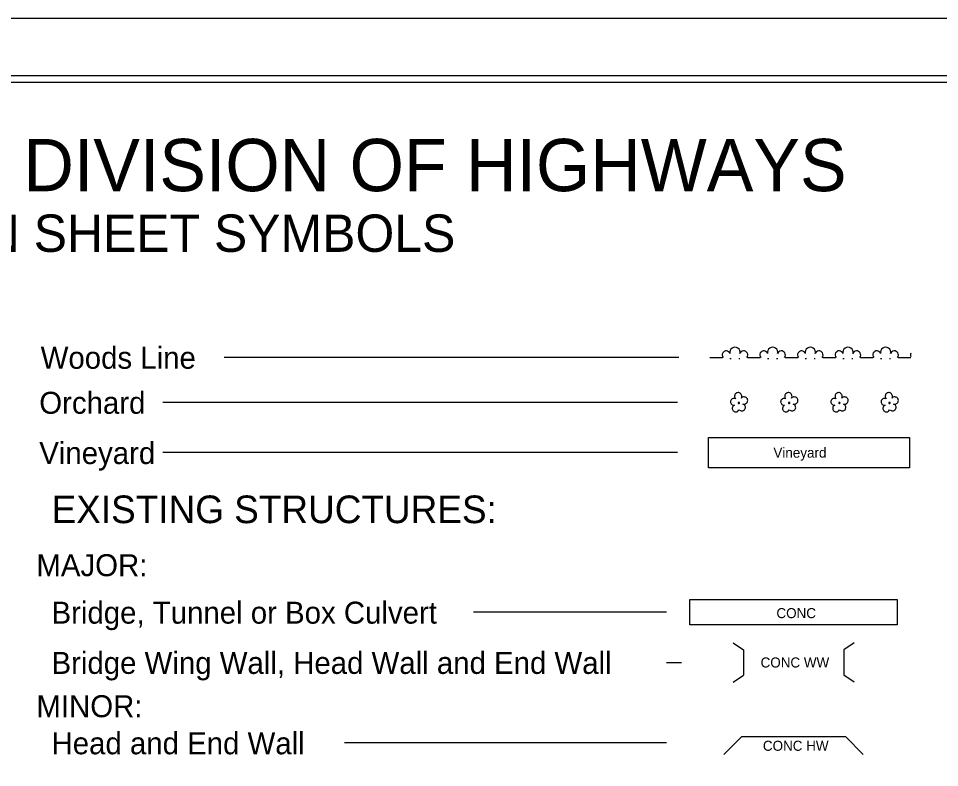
# Model space of a CAD drawing. Extents: x 2594871.4 to 2594905.1, y 784137.6 to 784159.6.
# Drawn here: x 2594889.82 to 2594897.02, y 784153.71 to 784159.56 of the extents above; entities that cross this region are included whole.
import ezdxf

# ---------------------------------------------------------------- set-up
doc = ezdxf.new("R2010")
doc.units = 0
for name, color, linetype in [('Default', 7, 'Continuous'), ('Sheet Plot Border Inside CELL', 7, 'Continuous'), ('Sheet Plot Border Outside CELL', 7, 'Continuous'), ('Sheet Symbology CELL', 7, 'Continuous')]:
    doc.layers.add(name, color=color, linetype=linetype)

msp = doc.modelspace()

# ---------------------------------------------------------------- linework, layer by layer
at = {"layer": 'Default'}
for p, q in [((2594894.9813, 784156.9155), (2594891.4285, 784156.9155)), ((2594895.2244, 784156.9155), (2594895.3225, 784156.9155)), ((2594895.3804, 784156.9057), (2594895.3902, 784156.9057)), ((2594895.449, 784156.9057), (2594895.4588, 784156.9057)), ((2594895.5187, 784156.9155), (2594895.6167, 784156.9155)), ((2594895.6746, 784156.9057), (2594895.6844, 784156.9057)), ((2594895.7433, 784156.9057), (2594895.7531, 784156.9057)), ((2594895.8129, 784156.9155), (2594895.911, 784156.9155)), ((2594895.9688, 784156.9057), (2594895.9786, 784156.9057)), ((2594896.0375, 784156.9057), (2594896.0473, 784156.9057)), ((2594896.1071, 784156.9155), (2594896.2052, 784156.9155)), ((2594896.2631, 784156.9057), (2594896.2729, 784156.9057)), ((2594896.3317, 784156.9057), (2594896.3415, 784156.9057)), ((2594896.4014, 784156.9155), (2594896.4994, 784156.9155)), ((2594896.5573, 784156.9057), (2594896.5671, 784156.9057)), ((2594896.626, 784156.9057), (2594896.6358, 784156.9057)), ((2594896.6956, 784156.9155), (2594896.7937, 784156.9155)), ((2594894.9703, 784156.5639), (2594890.9503, 784156.5639)), ((2594894.9703, 784156.1716), (2594890.9503, 784156.1716)), ((2594894.8856, 784154.9259), (2594893.3758, 784154.9259)), ((2594895.4044, 784154.6878), (2594895.4849, 784154.6316)), ((2594896.3499, 784154.6878), (2594896.2695, 784154.6316)), ((2594895.4849, 784154.6316), (2594895.4849, 784154.4355)), ((2594896.2695, 784154.6316), (2594896.2695, 784154.4355)), ((2594894.8856, 784154.5336), (2594895.0031, 784154.5336)), ((2594895.4044, 784154.3793), (2594895.4849, 784154.4355)), ((2594896.3499, 784154.3793), (2594896.2695, 784154.4355)), ((2594895.3338, 784153.8162), (2594895.4726, 784153.955)), ((2594895.4726, 784153.955), (2594896.2817, 784153.955)), ((2594896.2817, 784153.955), (2594896.4205, 784153.8162)), ((2594894.8856, 784153.906), (2594892.3689, 784153.906))]:
    msp.add_line(p, q, dxfattribs=at)
for points in [[(2594895.4693, 784156.5982), (2594895.4723, 784156.6041), (2594895.4732, 784156.61), (2594895.4723, 784156.6158), (2594895.4713, 784156.6217), (2594895.4683, 784156.6266), (2594895.4654, 784156.6315), (2594895.4605, 784156.6355), (2594895.4556, 784156.6384), (2594895.4487, 784156.6404), (2594895.4438, 784156.6404), (2594895.4379, 784156.6394), (2594895.4321, 784156.6374), (2594895.4272, 784156.6345), (2594895.4222, 784156.6306), (2594895.4193, 784156.6247), (2594895.4173, 784156.6198), (2594895.4164, 784156.6139), (2594895.4164, 784156.608), (2594895.4173, 784156.6021), (2594895.4203, 784156.5972), (2594895.4242, 784156.5913), (2594895.4193, 784156.5943), (2594895.4134, 784156.5953), (2594895.4075, 784156.5953), (2594895.4026, 784156.5933), (2594895.3977, 784156.5913), (2594895.3928, 784156.5874), (2594895.3889, 784156.5835), (2594895.386, 784156.5786), (2594895.385, 784156.5737), (2594895.384, 784156.5668), (2594895.385, 784156.5619), (2594895.3869, 784156.557), (2594895.3909, 784156.5521), (2594895.3938, 784156.5482), (2594895.3987, 784156.5452), (2594895.4046, 784156.5423), (2594895.4095, 784156.5413), (2594895.4154, 784156.5413), (2594895.4105, 784156.5393), (2594895.4056, 784156.5354), (2594895.4026, 784156.5315), (2594895.4007, 784156.5256), (2594895.3987, 784156.5197), (2594895.3987, 784156.5148), (2594895.3997, 784156.5089), (2594895.4026, 784156.504), (2594895.4056, 784156.4991), (2594895.4095, 784156.4952), (2594895.4144, 784156.4923), (2594895.4193, 784156.4903), (2594895.4252, 784156.4903), (2594895.4311, 784156.4903), (2594895.436, 784156.4913), (2594895.4409, 784156.4952), (2594895.4458, 784156.4982), (2594895.4507, 784156.507)], [(2594895.4507, 784156.507), (2594895.4625, 784156.5001), (2594895.4683, 784156.4982), (2594895.4742, 784156.4972), (2594895.4801, 784156.4982), (2594895.485, 784156.5001), (2594895.4899, 784156.5031), (2594895.4948, 784156.507), (2594895.4978, 784156.5119), (2594895.4997, 784156.5168), (2594895.5017, 784156.5227), (2594895.5007, 784156.5286), (2594895.4997, 784156.5344), (2594895.4958, 784156.5403), (2594895.4929, 784156.5443), (2594895.488, 784156.5472), (2594895.4821, 784156.5501), (2594895.488, 784156.5492), (2594895.4948, 784156.5492), (2594895.4997, 784156.5511), (2594895.5056, 784156.5541), (2594895.5105, 784156.557), (2594895.5144, 784156.5619), (2594895.5174, 784156.5678), (2594895.5184, 784156.5737), (2594895.5193, 784156.5796), (2594895.5184, 784156.5854), (2594895.5164, 784156.5913), (2594895.5125, 784156.5962), (2594895.5076, 784156.6011), (2594895.5027, 784156.6041), (2594895.4968, 784156.606), (2594895.4909, 784156.607), (2594895.485, 784156.607), (2594895.4791, 784156.6051), (2594895.4742, 784156.6021), (2594895.4693, 784156.5982)], [(2594895.8616, 784156.5982), (2594895.8646, 784156.6041), (2594895.8656, 784156.61), (2594895.8646, 784156.6158), (2594895.8636, 784156.6217), (2594895.8607, 784156.6266), (2594895.8577, 784156.6315), (2594895.8528, 784156.6355), (2594895.8479, 784156.6384), (2594895.841, 784156.6404), (2594895.8361, 784156.6404), (2594895.8302, 784156.6394), (2594895.8244, 784156.6374), (2594895.8195, 784156.6345), (2594895.8146, 784156.6306), (2594895.8116, 784156.6247), (2594895.8097, 784156.6198), (2594895.8087, 784156.6139), (2594895.8087, 784156.608), (2594895.8097, 784156.6021), (2594895.8126, 784156.5972), (2594895.8165, 784156.5913), (2594895.8116, 784156.5943), (2594895.8057, 784156.5953), (2594895.7998, 784156.5953), (2594895.7949, 784156.5933), (2594895.79, 784156.5913), (2594895.7851, 784156.5874), (2594895.7812, 784156.5835), (2594895.7783, 784156.5786), (2594895.7773, 784156.5737), (2594895.7763, 784156.5668), (2594895.7773, 784156.5619), (2594895.7792, 784156.557), (2594895.7832, 784156.5521), (2594895.7861, 784156.5482), (2594895.791, 784156.5452), (2594895.7969, 784156.5423), (2594895.8018, 784156.5413), (2594895.8077, 784156.5413), (2594895.8028, 784156.5393), (2594895.7979, 784156.5354), (2594895.7949, 784156.5315), (2594895.793, 784156.5256), (2594895.791, 784156.5197), (2594895.791, 784156.5148), (2594895.792, 784156.5089), (2594895.7949, 784156.504), (2594895.7979, 784156.4991), (2594895.8018, 784156.4952), (2594895.8067, 784156.4923), (2594895.8116, 784156.4903), (2594895.8175, 784156.4903), (2594895.8234, 784156.4903), (2594895.8283, 784156.4913), (2594895.8332, 784156.4952), (2594895.8381, 784156.4982), (2594895.843, 784156.507)], [(2594895.843, 784156.507), (2594895.8548, 784156.5001), (2594895.8607, 784156.4982), (2594895.8665, 784156.4972), (2594895.8724, 784156.4982), (2594895.8773, 784156.5001), (2594895.8822, 784156.5031), (2594895.8871, 784156.507), (2594895.8901, 784156.5119), (2594895.892, 784156.5168), (2594895.894, 784156.5227), (2594895.893, 784156.5286), (2594895.892, 784156.5344), (2594895.8881, 784156.5403), (2594895.8852, 784156.5443), (2594895.8803, 784156.5472), (2594895.8744, 784156.5501), (2594895.8803, 784156.5492), (2594895.8871, 784156.5492), (2594895.892, 784156.5511), (2594895.8979, 784156.5541), (2594895.9028, 784156.557), (2594895.9067, 784156.5619), (2594895.9097, 784156.5678), (2594895.9107, 784156.5737), (2594895.9117, 784156.5796), (2594895.9107, 784156.5854), (2594895.9087, 784156.5913), (2594895.9048, 784156.5962), (2594895.8999, 784156.6011), (2594895.895, 784156.6041), (2594895.8891, 784156.606), (2594895.8832, 784156.607), (2594895.8773, 784156.607), (2594895.8714, 784156.6051), (2594895.8665, 784156.6021), (2594895.8616, 784156.5982)], [(2594896.2539, 784156.5982), (2594896.2569, 784156.6041), (2594896.2579, 784156.61), (2594896.2569, 784156.6158), (2594896.2559, 784156.6217), (2594896.253, 784156.6266), (2594896.25, 784156.6315), (2594896.2451, 784156.6355), (2594896.2402, 784156.6384), (2594896.2333, 784156.6404), (2594896.2284, 784156.6404), (2594896.2226, 784156.6394), (2594896.2167, 784156.6374), (2594896.2118, 784156.6345), (2594896.2069, 784156.6306), (2594896.2039, 784156.6247), (2594896.202, 784156.6198), (2594896.201, 784156.6139), (2594896.201, 784156.608), (2594896.202, 784156.6021), (2594896.2049, 784156.5972), (2594896.2088, 784156.5913), (2594896.2039, 784156.5943), (2594896.198, 784156.5953), (2594896.1922, 784156.5953), (2594896.1872, 784156.5933), (2594896.1823, 784156.5913), (2594896.1774, 784156.5874), (2594896.1735, 784156.5835), (2594896.1706, 784156.5786), (2594896.1696, 784156.5737), (2594896.1686, 784156.5668), (2594896.1696, 784156.5619), (2594896.1716, 784156.557), (2594896.1755, 784156.5521), (2594896.1784, 784156.5482), (2594896.1833, 784156.5452), (2594896.1892, 784156.5423), (2594896.1941, 784156.5413), (2594896.2, 784156.5413), (2594896.1951, 784156.5393), (2594896.1902, 784156.5354), (2594896.1872, 784156.5315), (2594896.1853, 784156.5256), (2594896.1833, 784156.5197), (2594896.1833, 784156.5148), (2594896.1843, 784156.5089), (2594896.1872, 784156.504), (2594896.1902, 784156.4991), (2594896.1941, 784156.4952), (2594896.199, 784156.4923), (2594896.2039, 784156.4903), (2594896.2098, 784156.4903), (2594896.2157, 784156.4903), (2594896.2206, 784156.4913), (2594896.2255, 784156.4952), (2594896.2304, 784156.4982), (2594896.2353, 784156.507)], [(2594896.2353, 784156.507), (2594896.2471, 784156.5001), (2594896.253, 784156.4982), (2594896.2588, 784156.4972), (2594896.2647, 784156.4982), (2594896.2696, 784156.5001), (2594896.2745, 784156.5031), (2594896.2794, 784156.507), (2594896.2824, 784156.5119), (2594896.2843, 784156.5168), (2594896.2863, 784156.5227), (2594896.2853, 784156.5286), (2594896.2843, 784156.5344), (2594896.2804, 784156.5403), (2594896.2775, 784156.5443), (2594896.2726, 784156.5472), (2594896.2667, 784156.5501), (2594896.2726, 784156.5492), (2594896.2794, 784156.5492), (2594896.2843, 784156.5511), (2594896.2902, 784156.5541), (2594896.2951, 784156.557), (2594896.2991, 784156.5619), (2594896.302, 784156.5678), (2594896.303, 784156.5737), (2594896.304, 784156.5796), (2594896.303, 784156.5854), (2594896.301, 784156.5913), (2594896.2971, 784156.5962), (2594896.2922, 784156.6011), (2594896.2873, 784156.6041), (2594896.2814, 784156.606), (2594896.2755, 784156.607), (2594896.2696, 784156.607), (2594896.2637, 784156.6051), (2594896.2588, 784156.6021), (2594896.2539, 784156.5982)], [(2594896.6463, 784156.5982), (2594896.6492, 784156.6041), (2594896.6502, 784156.61), (2594896.6492, 784156.6158), (2594896.6482, 784156.6217), (2594896.6453, 784156.6266), (2594896.6423, 784156.6315), (2594896.6374, 784156.6355), (2594896.6325, 784156.6384), (2594896.6257, 784156.6404), (2594896.6208, 784156.6404), (2594896.6149, 784156.6394), (2594896.609, 784156.6374), (2594896.6041, 784156.6345), (2594896.5992, 784156.6306), (2594896.5962, 784156.6247), (2594896.5943, 784156.6198), (2594896.5933, 784156.6139), (2594896.5933, 784156.608), (2594896.5943, 784156.6021), (2594896.5972, 784156.5972), (2594896.6011, 784156.5913), (2594896.5962, 784156.5943), (2594896.5903, 784156.5953), (2594896.5845, 784156.5953), (2594896.5796, 784156.5933), (2594896.5747, 784156.5913), (2594896.5698, 784156.5874), (2594896.5658, 784156.5835), (2594896.5629, 784156.5786), (2594896.5619, 784156.5737), (2594896.5609, 784156.5668), (2594896.5619, 784156.5619), (2594896.5639, 784156.557), (2594896.5678, 784156.5521), (2594896.5707, 784156.5482), (2594896.5756, 784156.5452), (2594896.5815, 784156.5423), (2594896.5864, 784156.5413), (2594896.5923, 784156.5413), (2594896.5874, 784156.5393), (2594896.5825, 784156.5354), (2594896.5796, 784156.5315), (2594896.5776, 784156.5256), (2594896.5756, 784156.5197), (2594896.5756, 784156.5148), (2594896.5766, 784156.5089), (2594896.5796, 784156.504), (2594896.5825, 784156.4991), (2594896.5864, 784156.4952), (2594896.5913, 784156.4923), (2594896.5962, 784156.4903), (2594896.6021, 784156.4903), (2594896.608, 784156.4903), (2594896.6129, 784156.4913), (2594896.6178, 784156.4952), (2594896.6227, 784156.4982), (2594896.6276, 784156.507)], [(2594896.6276, 784156.507), (2594896.6394, 784156.5001), (2594896.6453, 784156.4982), (2594896.6512, 784156.4972), (2594896.657, 784156.4982), (2594896.6619, 784156.5001), (2594896.6668, 784156.5031), (2594896.6718, 784156.507), (2594896.6747, 784156.5119), (2594896.6767, 784156.5168), (2594896.6786, 784156.5227), (2594896.6776, 784156.5286), (2594896.6767, 784156.5344), (2594896.6727, 784156.5403), (2594896.6698, 784156.5443), (2594896.6649, 784156.5472), (2594896.659, 784156.5501), (2594896.6649, 784156.5492), (2594896.6718, 784156.5492), (2594896.6767, 784156.5511), (2594896.6825, 784156.5541), (2594896.6874, 784156.557), (2594896.6914, 784156.5619), (2594896.6943, 784156.5678), (2594896.6953, 784156.5737), (2594896.6963, 784156.5796), (2594896.6953, 784156.5854), (2594896.6933, 784156.5913), (2594896.6894, 784156.5962), (2594896.6845, 784156.6011), (2594896.6796, 784156.6041), (2594896.6737, 784156.606), (2594896.6678, 784156.607), (2594896.6619, 784156.607), (2594896.6561, 784156.6051), (2594896.6512, 784156.6021), (2594896.6463, 784156.5982)], [(2594895.4527, 784156.5639), (2594895.4497, 784156.5639), (2594895.4477, 784156.5629), (2594895.4458, 784156.5619), (2594895.4458, 784156.559), (2594895.4458, 784156.557), (2594895.4477, 784156.555), (2594895.4507, 784156.555), (2594895.4527, 784156.555), (2594895.4546, 784156.557), (2594895.4556, 784156.5599), (2594895.4546, 784156.5619), (2594895.4527, 784156.5639)], [(2594895.845, 784156.5639), (2594895.842, 784156.5639), (2594895.8401, 784156.5629), (2594895.8381, 784156.5619), (2594895.8381, 784156.559), (2594895.8381, 784156.557), (2594895.8401, 784156.555), (2594895.843, 784156.555), (2594895.845, 784156.555), (2594895.8469, 784156.557), (2594895.8479, 784156.5599), (2594895.8469, 784156.5619), (2594895.845, 784156.5639)], [(2594896.2373, 784156.5639), (2594896.2343, 784156.5639), (2594896.2324, 784156.5629), (2594896.2304, 784156.5619), (2594896.2304, 784156.559), (2594896.2304, 784156.557), (2594896.2324, 784156.555), (2594896.2353, 784156.555), (2594896.2373, 784156.555), (2594896.2392, 784156.557), (2594896.2402, 784156.5599), (2594896.2392, 784156.5619), (2594896.2373, 784156.5639)], [(2594896.6296, 784156.5639), (2594896.6266, 784156.5639), (2594896.6247, 784156.5629), (2594896.6227, 784156.5619), (2594896.6227, 784156.559), (2594896.6227, 784156.557), (2594896.6247, 784156.555), (2594896.6276, 784156.555), (2594896.6296, 784156.555), (2594896.6315, 784156.557), (2594896.6325, 784156.5599), (2594896.6315, 784156.5619), (2594896.6296, 784156.5639)], [(2594895.2133, 784156.2892), (2594896.7826, 784156.2892), (2594896.7826, 784156.0539), (2594895.2133, 784156.0539), (2594895.2133, 784156.2892)], [(2594895.068, 784155.0239), (2594896.6863, 784155.0239), (2594896.6863, 784154.8278), (2594895.068, 784154.8278), (2594895.068, 784155.0239)]]:
    msp.add_lwpolyline(points, dxfattribs=at)
for centre, radius, start, end in [((2594895.351, 784156.9354), 0.031, 18.43495, 219.23152), ((2594895.4196, 784156.955), 0.0404, 345.96376, 194.03624), ((2594895.4883, 784156.9354), 0.031, 320.76848, 161.56505), ((2594895.6451, 784156.9354), 0.031, 18.43495, 219.23152), ((2594895.7138, 784156.955), 0.0404, 345.96376, 194.03624), ((2594895.7824, 784156.9354), 0.031, 320.76848, 161.56505), ((2594895.9394, 784156.9354), 0.031, 18.43495, 219.23152), ((2594896.008, 784156.955), 0.0404, 345.96376, 194.03624), ((2594896.0767, 784156.9354), 0.031, 320.76848, 161.56505), ((2594896.2336, 784156.9354), 0.031, 18.43495, 219.23152), ((2594896.3022, 784156.955), 0.0404, 345.96376, 194.03624), ((2594896.3709, 784156.9354), 0.031, 320.76848, 161.56505), ((2594896.5278, 784156.9354), 0.031, 18.43495, 219.23152), ((2594896.5965, 784156.955), 0.0404, 345.96376, 194.03624), ((2594896.6651, 784156.9354), 0.031, 320.76848, 161.56505), ((2594896.8221, 784156.9354), 0.031, 156.25102, 203.74899)]:
    msp.add_arc(centre, radius, start, end, dxfattribs=at)
at = {"layer": 'Sheet Plot Border Inside CELL'}
msp.add_lwpolyline([(2594871.6321, 784138.0107), (2594904.9621, 784138.0107), (2594904.9621, 784159.1127), (2594871.6321, 784159.1127)], close=True, dxfattribs=at)
at = {"layer": 'Sheet Plot Border Outside CELL'}
msp.add_lwpolyline([(2594905.0521, 784159.5617), (2594871.3721, 784159.5617), (2594871.3721, 784137.5617), (2594905.0521, 784137.5617)], close=True, dxfattribs=at)
at = {"layer": 'Sheet Symbology CELL'}
msp.add_lwpolyline([(2594904.7121, 784159.0617), (2594874.7121, 784159.0617), (2594874.7121, 784138.0821), (2594904.7121, 784138.0821)], close=True, dxfattribs=at)

# ---------------------------------------------------------------- texts
at = {"layer": 'Default'}
for s, height, rotation, p in [('STATE OF NORTH CAROLINA, DIVISION OF HIGHWAYS', 0.408275, 360, (2594881.8527, 784158.2129)), ('CONVENTIONAL  PLAN SHEET SYMBOLS', 0.291625, 360, (2594885.5203, 784157.7392)), ('Woods Line', 0.17164, 360, (2594889.9958, 784156.8267)), ('Orchard', 0.17164, 360, (2594889.9847, 784156.4751)), ('Vineyard', 0.17164, 360, (2594889.9847, 784156.0828)), ('Vineyard', 0.07846, 0.00002, (2594895.7199, 784156.1323)), ('EXISTING STRUCTURES:', 0.21577, 360, (2594890.0806, 784155.6212)), ('MAJOR:', 0.17164, 360, (2594889.9624, 784155.2071)), ('Bridge, Tunnel or Box Culvert', 0.171636, 360, (2594890.0806, 784154.8366)), ('CONC', 0.07846, 360, (2594895.7435, 784154.8795)), ('Bridge Wing Wall, Head Wall and End Wall', 0.171636, 360, (2594890.0806, 784154.4443)), ('CONC WW', 0.07846, 0.00002, (2594895.6197, 784154.4943)), ('MINOR:', 0.17164, 360, (2594889.9624, 784154.1062)), ('Head and End Wall', 0.171636, 360, (2594890.0806, 784153.8167)), ('CONC HW', 0.07846, 360, (2594895.6379, 784153.8439))]:
    msp.add_text(s, height=height, rotation=rotation, dxfattribs=at).set_placement(p)

doc.saveas('drawing.dxf')
